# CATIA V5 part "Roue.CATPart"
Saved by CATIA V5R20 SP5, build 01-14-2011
Part number: Roue
Bounding box of the stored display mesh (mm): x -180 to -140, y -344.953 to -305.047, z -30 to 30
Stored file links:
  U:\CFAO\Thinkmotion\Roue.CATPart
  U:\CFAO\Thinkmotion\Bras Articule.CATProduct
  U:\CFAO\Thinkmotion\Squelette Roue.CATPart
  U:\CFAO\Thinkmotion\Bielle principale.CATPart
  U:\CFAO\Thinkmotion\Squelette Bielle principale.CATPart
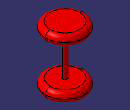
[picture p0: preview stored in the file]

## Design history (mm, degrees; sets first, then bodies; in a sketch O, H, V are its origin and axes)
Set1
  Plane1: linked copy from another document
  Point1: linked copy from another document
  DatumPoint1: linked copy from another document
Body1 (main body)
  Sketch1 on Plane1, origin (0, 0, 0), H (1, 0, 0), V (0, 1, 0)
    circle A1 centre (-160, -325) radius 2.5
    reference projected point E1 (-160, -325) from Point1
    radius A1 = 2.5
    concentricity: E1 A1
  Pad1: profile Sketch1, direction (0, 0, 1), length 30, mirrored extent
  Sketch2 on end face of Pad1, origin (0, 0, 30), H (1, 0, 0), V (0, 1, 0)
    circle A1 centre (-160, -325) radius 20
    reference projected point E1 (-160, -325) from vertex of DatumPoint1
    reference projected point E2 (-160, -325) from DatumPoint1
    radius A1 = 20
    concentricity: A1 E1, E2 A1
  Pad2: profile Sketch2, direction (0, 0, -1), length 10
  Fillet1: radius 5, on edge [face of Pad2 from Sketch2.A1 | face of Pad2]; edge [end face of Pad2 | face of Pad2 from Sketch2.A1]
  Sketch3 on start face of Pad1, origin (0, 0, -30), H (1, 0, 0), V (0, -1, 0)
    circle A1 centre (-160, 325) radius 20
    reference projected point E1 (-160, 325) from DatumPoint1
    radius A1 = 20
    concentricity: A1 E1
  Pad3: profile Sketch3, direction (0, 0, 1), length 10
  Fillet2: radius 5, on edge [end face of Pad3 | face of Pad3 from Sketch3.A1]; edge [face of Pad3 from Sketch3.A1 | face of Pad3]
